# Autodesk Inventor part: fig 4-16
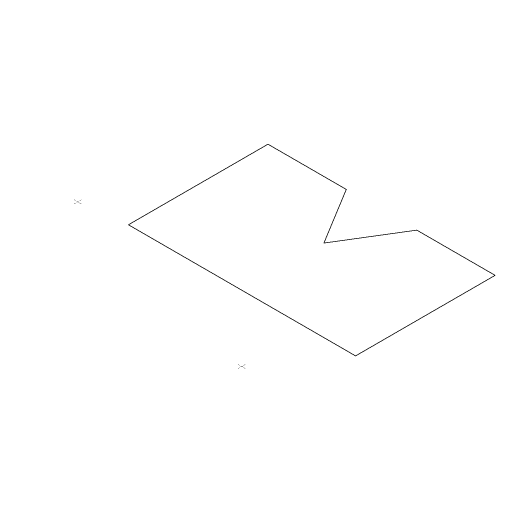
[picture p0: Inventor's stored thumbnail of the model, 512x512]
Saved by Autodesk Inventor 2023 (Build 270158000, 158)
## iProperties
Created: 2005-02
Part Number: fig 4-16
Document SubType Name: Modeling
Designer: CADCIM
Manufacturer: Standard
Standards Organization: Custom
Density: 1 g/cm^3
Material: Generic
Appearance: Default
Author: CADCIM
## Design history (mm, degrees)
sketch "Sketch1"
  geometry: L1 (-25.19, 27.524)-(-25.19, 5.557); L2 (-25.19, 5.557)-(10.567, 5.557); L3 (10.567, 5.557)-(10.567, 27.524); L4 (10.567, 27.524)-(-1.76, 27.524); L5 (-1.76, 27.524)-(-7.312, 18.449); L6 (-7.312, 18.449)-(-12.863, 27.524); L7 (-12.863, 27.524)-(-25.19, 27.524); 2 further points
  constraints: 14 end point, 3 equal length, 3 parallel, 1 perpendicular, 1 vertical, 1 other
